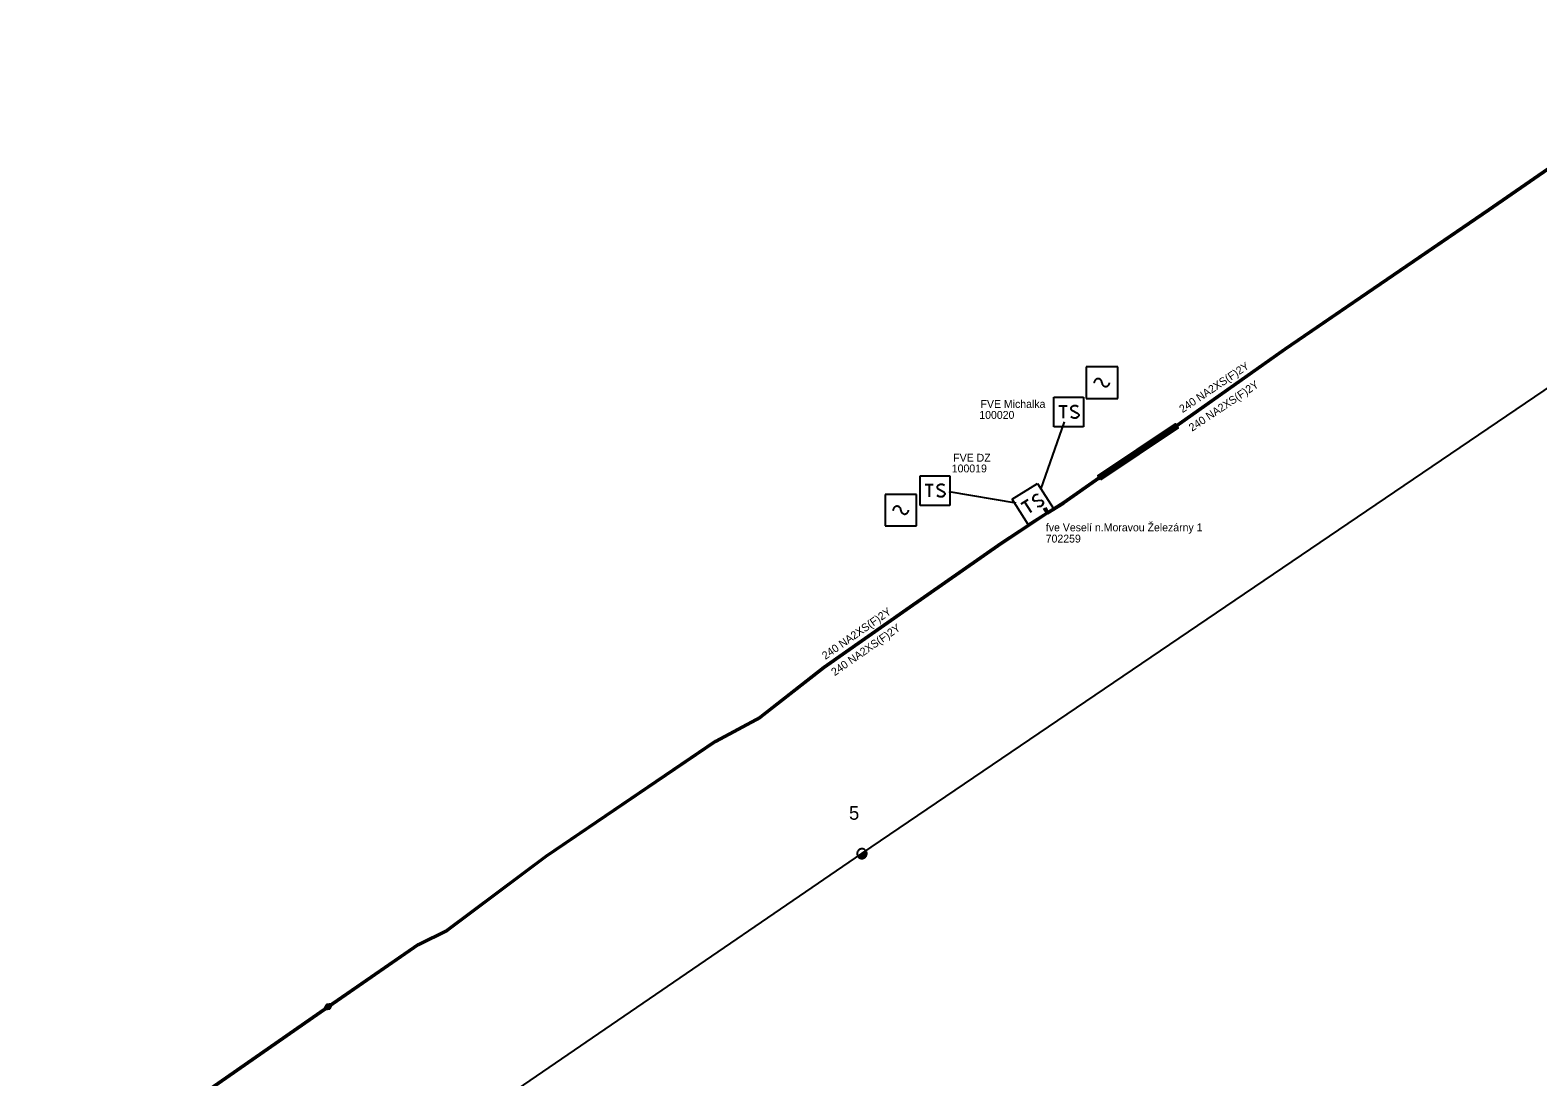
# Model space of a CAD drawing. Extents: x -545588 to -543214, y -1196037 to -1194452.
# Drawn here: x -545008.8 to -544817.1, y -1194764.6 to -1194631.4 of the extents above; entities that cross this region are included whole.
import ezdxf

# ---------------------------------------------------------------- set-up
doc = ezdxf.new("R2010")
doc.units = 0
for name, color, linetype in [('Vrstva 1', 7, 'Continuous'), ('Vrstva 13', 7, 'Continuous'), ('Vrstva 14', 7, 'Continuous'), ('Vrstva 19', 7, 'Continuous'), ('Vrstva 2', 7, 'Continuous'), ('Vrstva 20', 7, 'Continuous'), ('Vrstva 25', 7, 'Continuous'), ('Vrstva 26', 7, 'Continuous'), ('Vrstva 27', 7, 'Continuous'), ('Vrstva 34', 7, 'Continuous'), ('Vrstva 4', 7, 'Continuous'), ('Vrstva 5', 7, 'Continuous'), ('Vrstva 6', 7, 'Continuous')]:
    doc.layers.add(name, color=color, linetype=linetype)

# ---------------------------------------------------------------- blocks, each defined once
blk = doc.blocks.new('VN440')
at = {"layer": 'Vrstva 2'}
for points in [[(1.22, 0), (1.21, 0.13), (1.19, 0.25), (1.16, 0.38), (1.11, 0.5), (1.05, 0.61), (0.98, 0.72), (0.9, 0.82), (0.81, 0.91), (0.71, 0.99), (0.6, 1.06), (0.49, 1.12), (0.37, 1.16), (0.25, 1.2), (0.12, 1.22), (-0.01, 1.22), (-0.14, 1.22), (-0.26, 1.2), (-0.39, 1.16), (-0.51, 1.12), (-0.62, 1.06), (-0.73, 0.99), (-0.83, 0.91), (-0.92, 0.82), (-1, 0.72), (-1.07, 0.61), (-1.13, 0.5), (-1.18, 0.38), (-1.21, 0.25), (-1.23, 0.13), (-1.24, 0), (-1.23, -0.13), (-1.21, -0.26), (-1.18, -0.38), (-1.13, -0.5), (-1.07, -0.62), (-1, -0.73), (-0.92, -0.83), (-0.83, -0.92), (-0.73, -1), (-0.62, -1.07), (-0.51, -1.13), (-0.39, -1.17), (-0.26, -1.2), (-0.14, -1.23), (-0.01, -1.23), (0.12, -1.23), (0.25, -1.2), (0.37, -1.17), (0.49, -1.13), (0.6, -1.07), (0.71, -1), (0.81, -0.92), (0.9, -0.83), (0.98, -0.73), (1.05, -0.62), (1.11, -0.5), (1.16, -0.38), (1.19, -0.26), (1.21, -0.13), (1.22, 0)], [(-1.24, 0), (1.22, 0)], [(-1.18, -0.34), (1.1, -0.34)], [(-1.01, -0.63), (0.97, -0.63)], [(-0.74, -0.92), (0.68, -0.92)]]:
    blk.add_lwpolyline(points, dxfattribs=at)
blk = doc.blocks.new('VN870')
at = {"layer": 'Vrstva 4'}
for points in [[(0, -0.25), (0.5, 0), (0, 0.25), (-0.5, 0), (0, -0.25)], [(0.37, 0), (0, 0.19), (-0.36, 0), (0, -0.19), (0.37, 0)], [(0.24, 0), (0, 0.12), (-0.25, 0), (0, -0.12), (0.24, 0)], [(0.12, 0), (0, 0.06), (-0.13, 0), (0, -0.06), (0.12, 0)]]:
    blk.add_lwpolyline(points, dxfattribs=at)
blk = doc.blocks.new('VN740')
at = {"layer": 'Vrstva 1'}
for points in [[(2, 2), (-2, 2)], [(-2, 2), (-2, -2)], [(2, -2), (2, 2)], [(0, 0), (0, 0.05), (-0.01, 0.1), (-0.02, 0.15), (-0.04, 0.2), (-0.06, 0.24), (-0.09, 0.29), (-0.12, 0.33), (-0.16, 0.36), (-0.2, 0.4), (-0.24, 0.42), (-0.29, 0.45), (-0.34, 0.47), (-0.38, 0.48), (-0.44, 0.49), (-0.49, 0.49), (-0.54, 0.49), (-0.59, 0.48), (-0.64, 0.47), (-0.69, 0.45), (-0.73, 0.43), (-0.77, 0.4), (-0.81, 0.37), (-0.85, 0.33), (-0.88, 0.29), (-0.91, 0.25), (-0.93, 0.2), (-0.95, 0.16), (-0.97, 0.11), (-0.97, 0.06), (-0.98, 0), (-0.98, 0)], [(0, 0), (0, -0.05), (0.01, -0.1), (0.02, -0.15), (0.04, -0.2), (0.06, -0.24), (0.09, -0.28), (0.12, -0.32), (0.15, -0.36), (0.19, -0.39), (0.23, -0.42), (0.28, -0.44), (0.32, -0.46), (0.37, -0.48), (0.42, -0.49), (0.47, -0.49), (0.52, -0.49), (0.57, -0.48), (0.62, -0.47), (0.67, -0.45), (0.71, -0.43), (0.75, -0.4), (0.79, -0.37), (0.83, -0.34), (0.86, -0.3), (0.89, -0.26), (0.91, -0.21), (0.93, -0.17), (0.95, -0.12), (0.96, -0.07), (0.96, -0.02), (0.96, -0.02)], [(-2, -2), (2, -2)]]:
    blk.add_lwpolyline(points, dxfattribs=at)
blk = doc.blocks.new('VN640')
at = {"layer": 'Vrstva 6'}
for points in [[(-1.89, 1.89), (1.89, 1.89)], [(-1.89, -1.89), (-1.89, 1.89)], [(-1.26, 0.79), (-0.22, 0.79)], [(-0.73, 0.79), (-0.73, -0.79)], [(1.2, 0.66), (0.94, 0.79), (0.66, 0.79), (0.41, 0.66), (0.28, 0.47), (0.28, 0.41), (0.41, 0.22), (1.13, -0.16), (1.26, -0.32), (1.26, -0.47), (1.13, -0.66), (0.91, -0.79), (0.63, -0.79), (0.5, -0.73), (0.28, -0.6)], [(1.89, 1.89), (1.89, -1.89)], [(1.89, -1.89), (-1.89, -1.89)]]:
    blk.add_lwpolyline(points, dxfattribs=at)

msp = doc.modelspace()

# ---------------------------------------------------------------- linework, layer by layer
at = {"layer": 'Vrstva 1'}
msp.add_lwpolyline([(-545096.16, -1194848.04), (-545075.95, -1194854.58), (-545032.81, -1194825.14), (-544993.69, -1194798.32), (-544903.01, -1194736.22), (-544804.37, -1194669.21), (-544702.68, -1194600.1), (-544611.95, -1194519.78), (-544514.29, -1194451.62)], dxfattribs=at)
at = {"layer": 'Vrstva 20'}
msp.add_lwpolyline([(-544872.66, -1194688.66), (-544873, -1194688.16), (-544863.15, -1194681.54), (-544862.81, -1194682.04)], close=True, dxfattribs=at)
at = {"layer": 'Vrstva 5'}
for points in [[(-544879.69, -1194692.19), (-544879.38, -1194692.72), (-544877.42, -1194691.5), (-544872.89, -1194688.33), (-544863.04, -1194681.71), (-544849.25, -1194671.95), (-544823.31, -1194654.21), (-544796.7, -1194635.8), (-544769.45, -1194617.2), (-544745.44, -1194600.7), (-544712.88, -1194578.62), (-544686.33, -1194560.51), (-544663.49, -1194544.51), (-544638.43, -1194527.34), (-544613.5, -1194510.21), (-544588.16, -1194493), (-544563.72, -1194476.13), (-544542.28, -1194461.2), (-544536.69, -1194457.31), (-544535.63, -1194456.59)], [(-545017.49, -1194788.17), (-544994.72, -1194772.48), (-544991.46, -1194771.51), (-544987.68, -1194767.54), (-544970.83, -1194755.78), (-544959.36, -1194747.87), (-544955.67, -1194746.06), (-544943.12, -1194736.64), (-544921.55, -1194722), (-544915.88, -1194718.94), (-544907.79, -1194712.62), (-544897.27, -1194705.22), (-544885.19, -1194696.78), (-544879.36, -1194692.94), (-544877.31, -1194691.66), (-544872.77, -1194688.49), (-544862.92, -1194681.87), (-544849.13, -1194672.11), (-544823.19, -1194654.37), (-544796.58, -1194635.96)], [(-544880.28, -1194689.86), (-544877.25, -1194681.26)], [(-544883.39, -1194691.6), (-544891.93, -1194690.16)], [(-545233.41, -1194894.88), (-545178.88, -1194890.69), (-545165.68, -1194889.55), (-545162.68, -1194888.62), (-545146.55, -1194877.89), (-545122.2, -1194861.06), (-545095.47, -1194842.73), (-545060.25, -1194817.94), (-545034.96, -1194800.14), (-545017.61, -1194788.01), (-544994.8, -1194772.3), (-544991.56, -1194771.33), (-544987.81, -1194767.38), (-544970.95, -1194755.62), (-544959.46, -1194747.69), (-544955.77, -1194745.88), (-544943.24, -1194736.48), (-544921.65, -1194721.82), (-544915.98, -1194718.78), (-544907.91, -1194712.46), (-544897.39, -1194705.06), (-544885.31, -1194696.62), (-544879.55, -1194692.83), (-544879.87, -1194692.29)]]:
    msp.add_lwpolyline(points, dxfattribs=at)

# ---------------------------------------------------------------- block references
at = {"layer": 'Vrstva 13', "xscale": 0.5, "yscale": 0.5, "rotation": 34.40455542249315}
msp.add_blockref('VN440', (-544903.01, -1194736.22), dxfattribs=at)
at = {"layer": 'Vrstva 19'}
for p, rotation in [((-544970.95, -1194755.62), 34.91301949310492), ((-544970.83, -1194755.78), 34.91111663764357)]:
    msp.add_blockref('VN870', p, dxfattribs=dict(at, rotation=rotation))
at = {"layer": 'Vrstva 25'}
for p in [(-544876.71, -1194680.02), (-544893.73, -1194690.03)]:
    msp.add_blockref('VN640', p, dxfattribs=at)
at = {"layer": 'Vrstva 25', "rotation": 32.363291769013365}
msp.add_blockref('VN640', (-544881.28, -1194691.71), dxfattribs=at)
at = {"layer": 'Vrstva 34'}
for p in [(-544872.49, -1194676.28), (-544898.06, -1194692.51)]:
    msp.add_blockref('VN740', p, dxfattribs=at)

# ---------------------------------------------------------------- texts
at = {"layer": 'Vrstva 14'}
msp.add_text('5', height=1.75, dxfattribs=at).set_placement((-544904.66, -1194731.91))
at = {"layer": 'Vrstva 26'}
for s, p in [('100020', (-544888.09, -1194680.89)), ('100019', (-544891.59, -1194687.7)), ('702259', (-544879.64, -1194696.63))]:
    msp.add_text(s, height=1, dxfattribs=at).set_placement(p)
at = {"layer": 'Vrstva 27'}
for s, p in [('FVE Michalka', (-544887.93, -1194679.49)), ('FVE DZ', (-544891.4, -1194686.34)), ('fve Veselí n.Moravou Železárny 1', (-544879.62, -1194695.2))]:
    msp.add_text(s, height=1, dxfattribs=at).set_placement(p)
at = {"layer": 'Vrstva 6'}
for rotation, p in [(33.904, (-544862.24, -1194680.17)), (33.904, (-544861.02, -1194682.54)), (34.942, (-544907.66, -1194711.57)), (34.94, (-544906.49, -1194713.65))]:
    msp.add_text('240 NA2XS(F)2Y', height=1, rotation=rotation, dxfattribs=at).set_placement(p)

doc.saveas('drawing.dxf')
